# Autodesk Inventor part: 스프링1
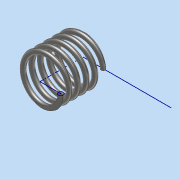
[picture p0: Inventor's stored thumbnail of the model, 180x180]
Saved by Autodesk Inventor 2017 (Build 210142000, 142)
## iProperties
Part Number: 스프링1
Material: 스테인레스 스틸
Document SubType Name: Modeling
Designer: MRC
Density: 8 g/cm^3
Appearance: 반연마
Mass: 6.55763 g
Surface Area: 16.7052 cm^2
Volume: 0.819704 cm^3
Author: MRC
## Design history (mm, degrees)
sketch "스케치1"
  geometry: L1 (0, 0)-(0, 17.5); L2 (0, 0)-(8.5, 0); L3 (0, 17.5)-(36.027, 17.5); C1 r 1 at (8.5, 0)
  constraints: 6 end point, 2 horizontal, 1 centre point, 1 coincident, 1 vertical
  dimensions: "d0" = 17.5 distance of L1.start L1.end (derived); "d2" = 2 diameter of C1; "d3" = 17 diameter of L2.end L1
feature "코일1" pitch "d4" = 10; turns "d6" = 5; dims "d5" = 17.5 (= d0), "d7" = 0, angle "d8" = 90 deg, angle "d9" = 90 deg, "d10" = 0, "d11" = 0
sketch "스케치2"
  geometry: L1 (17.5, 10)-(0, 10); L2 (0, 10)-(0, -10); L3 (0, -10)-(17.5, -10); L4 (17.5, -10)-(17.5, 10); 2 further points
  constraints: 8 end point, 2 parallel, 1 coincident, 1 horizontal, 1 midpoint, 1 perpendicular
  dimensions: "d12" = 20 distance of L3.end L1.start; "d13" = 17.5 distance of L2.end L3.end (= d0)
extrude "돌출1" sketch "스케치2" stored distance "d14" = 0; taper "d15" = 0 deg
node "솔리드1"
